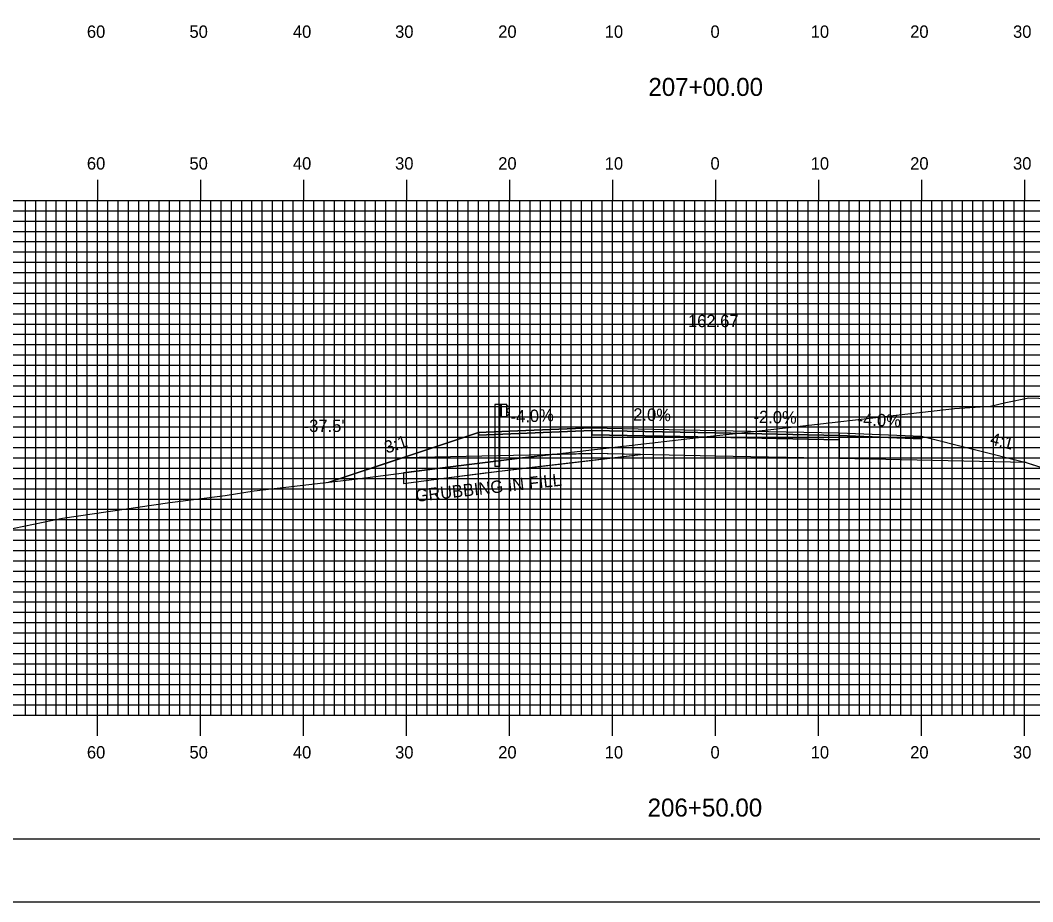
# Model space of a CAD drawing. Extents: x 1793666 to 1794009, y 442591 to 442811.
# Drawn here: x 1793763.8 to 1793862.1, y 442590.5 to 442676.2 of the extents above; entities that cross this region are included whole.
import ezdxf

# ---------------------------------------------------------------- set-up
doc = ezdxf.new("R2010")
doc.units = 0
for name, color, linetype in [('ANNOTATION', 7, 'Continuous'), ('BORDER', 7, 'Continuous'), ('D_Guardrail_Beam_Lt', 7, 'Continuous'), ('D_Roadway_Centerline', 7, 'Continuous'), ('D_Roadway_Centerline_Text', 7, 'Continuous'), ('D_Roadway_Edge_Shoulder', 7, 'Continuous'), ('D_Roadway_Edge_TW', 7, 'Continuous'), ('D_Roadway_FinishedGrade', 7, 'Continuous'), ('D_Roadway_Pavement', 7, 'Continuous'), ('D_Roadway_SlopeLines', 7, 'Continuous'), ('D_Roadway_SubGrade', 7, 'Continuous'), ('D_Text_Standard', 7, 'Continuous'), ('GRUBBING IN FILL', 7, 'Continuous'), ('H_V ANNOTATION', 7, 'Continuous'), ('MAJOR', 7, 'Continuous'), ('MINOR', 7, 'Continuous'), ('PLOT BOUNDARY', 7, 'Continuous'), ('S_Roadway_Centerline', 7, 'Continuous')]:
    doc.layers.add(name, color=color, linetype=linetype)

msp = doc.modelspace()

# ---------------------------------------------------------------- linework, layer by layer
at = {"layer": 'BORDER'}
msp.add_lwpolyline([(1793681.714, 442596.665), (1794001.714, 442596.665), (1794001.714, 442806.665), (1793681.714, 442806.665)], close=True, dxfattribs=at)
at = {"layer": 'D_Guardrail_Beam_Lt'}
for p, q in [((1793809.884, 442638.836), (1793809.884, 442632.836)), ((1793810.355, 442638.836), (1793809.884, 442638.836)), ((1793811.043, 442638.836), (1793810.355, 442638.836)), ((1793810.355, 442638.836), (1793810.355, 442637.669)), ((1793810.418, 442638.836), (1793810.418, 442637.669)), ((1793810.522, 442638.836), (1793810.522, 442637.669)), ((1793811.043, 442637.669), (1793811.043, 442638.836)), ((1793811.043, 442638.752), (1793811.117, 442638.738)), ((1793811.047, 442638.288), (1793811.047, 442638.217)), ((1793811.276, 442638.488), (1793811.081, 442638.352)), ((1793811.081, 442638.153), (1793811.276, 442638.017)), ((1793811.133, 442638.731), (1793811.276, 442638.631)), ((1793811.276, 442637.874), (1793811.133, 442637.774)), ((1793810.355, 442637.669), (1793811.043, 442637.669)), ((1793810.376, 442632.836), (1793810.376, 442637.669)), ((1793811.117, 442637.767), (1793811.043, 442637.752)), ((1793810.376, 442632.836), (1793809.884, 442632.836))]:
    msp.add_line(p, q, dxfattribs=at)
for centre, major_axis, start_param, end_param in [((1793811.126, 442638.288), (-0.0789, 0), 5.323254, 6.283185), ((1793811.126, 442638.217), (-0.0789, 0), 6.283185, 7.243116), ((1793811.109, 442638.697), (0.0417, 0), 0.959931, 1.376053), ((1793811.226, 442638.56), (0.0877, 0), 5.323254, 7.243116), ((1793811.226, 442637.945), (0.0877, 0), 5.323254, 7.243116), ((1793811.109, 442637.808), (0.0417, 0), 4.907132, 5.323254)]:
    msp.add_ellipse(centre, major_axis=major_axis, ratio=0.995501, start_param=start_param, end_param=end_param, dxfattribs=at)
at = {"layer": 'D_Roadway_Centerline'}
msp.add_lwpolyline([(1793793.811, 442631.298), (1793801.037, 442633.707), (1793808.314, 442636.132), (1793811.314, 442636.252), (1793819.314, 442636.572), (1793831.314, 442636.332), (1793843.314, 442636.092), (1793851.314, 442635.772), (1793861.488, 442633.229), (1793865.388, 442631.947), (1793869.289, 442630.665)], dxfattribs=at)
at = {"layer": 'D_Roadway_Edge_Shoulder'}
for points in [[(1793819.314, 442636.572), (1793811.314, 442636.252), (1793811.314, 442636.252), (1793808.314, 442636.132), (1793808.314, 442635.882), (1793819.314, 442636.322)], [(1793843.314, 442636.092), (1793851.314, 442635.772), (1793851.314, 442635.522), (1793843.314, 442635.842)]]:
    msp.add_lwpolyline(points, close=True, dxfattribs=at)
at = {"layer": 'D_Roadway_Edge_TW'}
msp.add_lwpolyline([(1793819.314, 442636.322), (1793819.314, 442636.572), (1793831.314, 442636.332), (1793843.314, 442636.092), (1793843.314, 442635.842), (1793831.314, 442636.082)], close=True, dxfattribs=at)
at = {"layer": 'D_Roadway_FinishedGrade'}
msp.add_line((1793861.488, 442633.229), (1793869.289, 442630.665), dxfattribs=at)
msp.add_line((1793861.488, 442633.229), (1793869.289, 442630.665), dxfattribs=at)
at = {"layer": 'D_Roadway_Pavement'}
msp.add_lwpolyline([(1793819.314, 442635.906), (1793819.314, 442636.322), (1793831.314, 442636.082), (1793843.314, 442635.842), (1793843.314, 442635.426), (1793831.314, 442635.666)], close=True, dxfattribs=at)
for points in [[(1793819.314, 442636.322), (1793819.314, 442635.906)], [(1793843.314, 442635.842), (1793843.314, 442635.426)]]:
    msp.add_lwpolyline(points, dxfattribs=at)
at = {"layer": 'D_Roadway_SlopeLines'}
msp.add_line((1793851.314, 442635.772), (1793861.488, 442633.229), dxfattribs=at)
msp.add_lwpolyline([(1793808.314, 442636.132), (1793793.616, 442631.233)], dxfattribs=at)
at = {"layer": 'D_Roadway_SubGrade'}
for points in [[(1793819.314, 442635.906), (1793819.314, 442636.322), (1793808.314, 442635.882), (1793808.314, 442636.132), (1793801.037, 442633.707), (1793819.314, 442634.072)], [(1793819.314, 442634.072), (1793819.314, 442636.322), (1793819.314, 442635.906), (1793831.314, 442635.666), (1793843.314, 442635.426), (1793843.314, 442635.842), (1793843.314, 442633.592), (1793831.314, 442633.832)], [(1793843.314, 442635.426), (1793843.314, 442635.842), (1793851.314, 442635.522), (1793851.314, 442635.772), (1793861.488, 442633.229), (1793843.314, 442633.592)]]:
    msp.add_lwpolyline(points, close=True, dxfattribs=at)
at = {"layer": 'GRUBBING IN FILL'}
msp.add_line((1793801.037, 442632.198), (1793801.037, 442631.189), dxfattribs=at)
msp.add_line((1793801.037, 442632.198), (1793801.037, 442631.189), dxfattribs=at)
msp.add_lwpolyline([(1793801.037, 442632.198), (1793801.037, 442631.189), (1793805.196, 442631.73), (1793808.942, 442632.201), (1793818.361, 442633.325), (1793824.034, 442633.978), (1793819.314, 442634.072), (1793815.442, 442633.995), (1793812.568, 442633.664), (1793805.069, 442632.722)], close=True, dxfattribs=at)
msp.add_lwpolyline([(1793801.037, 442632.198), (1793801.037, 442631.189), (1793805.196, 442631.73), (1793808.942, 442632.201), (1793818.361, 442633.325), (1793824.034, 442633.978), (1793819.314, 442634.072), (1793815.442, 442633.995), (1793812.568, 442633.664), (1793805.069, 442632.722)], close=True, dxfattribs=at)
msp.add_lwpolyline([(1793801.037, 442631.189), (1793805.196, 442631.73), (1793812.688, 442632.671), (1793824.034, 442633.978)], dxfattribs=at)
msp.add_lwpolyline([(1793801.037, 442631.189), (1793805.196, 442631.73), (1793812.688, 442632.671), (1793824.034, 442633.978)], dxfattribs=at)
at = {"layer": 'MAJOR'}
for p, q in [((1793771.314, 442660.669), (1793771.314, 442658.665)), ((1793781.314, 442660.669), (1793781.314, 442658.665)), ((1793791.314, 442660.669), (1793791.314, 442658.665)), ((1793801.314, 442660.669), (1793801.314, 442658.665)), ((1793811.314, 442660.669), (1793811.314, 442658.665)), ((1793821.314, 442660.669), (1793821.314, 442658.665)), ((1793831.314, 442660.669), (1793831.314, 442658.665)), ((1793841.314, 442660.669), (1793841.314, 442658.665)), ((1793851.314, 442660.669), (1793851.314, 442658.665)), ((1793861.314, 442660.669), (1793861.314, 442658.665)), ((1793691.314, 442658.665), (1793971.314, 442658.665)), ((1793691.314, 442658.665), (1793971.314, 442658.665)), ((1793771.314, 442608.665), (1793771.314, 442658.665)), ((1793781.314, 442608.665), (1793781.314, 442658.665)), ((1793791.314, 442608.665), (1793791.314, 442658.665)), ((1793801.314, 442608.665), (1793801.314, 442658.665)), ((1793811.314, 442608.665), (1793811.314, 442658.665)), ((1793821.314, 442608.665), (1793821.314, 442658.665)), ((1793831.314, 442608.665), (1793831.314, 442658.665)), ((1793841.314, 442608.665), (1793841.314, 442658.665)), ((1793851.314, 442608.665), (1793851.314, 442658.665)), ((1793861.314, 442608.665), (1793861.314, 442658.665)), ((1793691.314, 442653.665), (1793971.314, 442653.665)), ((1793691.314, 442648.665), (1793971.314, 442648.665)), ((1793691.314, 442643.665), (1793971.314, 442643.665)), ((1793691.314, 442638.665), (1793971.314, 442638.665)), ((1793691.314, 442633.665), (1793971.314, 442633.665)), ((1793691.314, 442628.665), (1793971.314, 442628.665)), ((1793691.314, 442623.665), (1793971.314, 442623.665)), ((1793691.314, 442618.665), (1793971.314, 442618.665)), ((1793691.314, 442613.665), (1793971.314, 442613.665)), ((1793691.314, 442608.665), (1793971.314, 442608.665)), ((1793691.314, 442608.665), (1793971.314, 442608.665)), ((1793771.314, 442606.661), (1793771.314, 442608.665)), ((1793781.314, 442606.661), (1793781.314, 442608.665)), ((1793791.314, 442606.661), (1793791.314, 442608.665)), ((1793801.314, 442606.661), (1793801.314, 442608.665)), ((1793811.314, 442606.661), (1793811.314, 442608.665)), ((1793821.314, 442606.661), (1793821.314, 442608.665)), ((1793831.314, 442606.661), (1793831.314, 442608.665)), ((1793841.314, 442606.661), (1793841.314, 442608.665)), ((1793851.314, 442606.661), (1793851.314, 442608.665)), ((1793861.314, 442606.661), (1793861.314, 442608.665))]:
    msp.add_line(p, q, dxfattribs=at)
at = {"layer": 'MINOR'}
for p, q in [((1793764.314, 442608.665), (1793764.314, 442658.665)), ((1793765.314, 442608.665), (1793765.314, 442658.665)), ((1793766.314, 442608.665), (1793766.314, 442658.665)), ((1793767.314, 442608.665), (1793767.314, 442658.665)), ((1793768.314, 442608.665), (1793768.314, 442658.665)), ((1793769.314, 442608.665), (1793769.314, 442658.665)), ((1793770.314, 442608.665), (1793770.314, 442658.665)), ((1793772.314, 442608.665), (1793772.314, 442658.665)), ((1793773.314, 442608.665), (1793773.314, 442658.665)), ((1793774.314, 442608.665), (1793774.314, 442658.665)), ((1793775.314, 442608.665), (1793775.314, 442658.665)), ((1793776.314, 442608.665), (1793776.314, 442658.665)), ((1793777.314, 442608.665), (1793777.314, 442658.665)), ((1793778.314, 442608.665), (1793778.314, 442658.665)), ((1793779.314, 442608.665), (1793779.314, 442658.665)), ((1793780.314, 442608.665), (1793780.314, 442658.665)), ((1793782.314, 442608.665), (1793782.314, 442658.665)), ((1793783.314, 442608.665), (1793783.314, 442658.665)), ((1793784.314, 442608.665), (1793784.314, 442658.665)), ((1793785.314, 442608.665), (1793785.314, 442658.665)), ((1793786.314, 442608.665), (1793786.314, 442658.665)), ((1793787.314, 442608.665), (1793787.314, 442658.665)), ((1793788.314, 442608.665), (1793788.314, 442658.665)), ((1793789.314, 442608.665), (1793789.314, 442658.665)), ((1793790.314, 442608.665), (1793790.314, 442658.665)), ((1793792.314, 442608.665), (1793792.314, 442658.665)), ((1793793.314, 442608.665), (1793793.314, 442658.665)), ((1793794.314, 442608.665), (1793794.314, 442658.665)), ((1793795.314, 442608.665), (1793795.314, 442658.665)), ((1793796.314, 442608.665), (1793796.314, 442658.665)), ((1793797.314, 442608.665), (1793797.314, 442658.665)), ((1793798.314, 442608.665), (1793798.314, 442658.665)), ((1793799.314, 442608.665), (1793799.314, 442658.665)), ((1793800.314, 442608.665), (1793800.314, 442658.665)), ((1793802.314, 442608.665), (1793802.314, 442658.665)), ((1793803.314, 442608.665), (1793803.314, 442658.665)), ((1793804.314, 442608.665), (1793804.314, 442658.665)), ((1793805.314, 442608.665), (1793805.314, 442658.665)), ((1793806.314, 442608.665), (1793806.314, 442658.665)), ((1793807.314, 442608.665), (1793807.314, 442658.665)), ((1793808.314, 442608.665), (1793808.314, 442658.665)), ((1793809.314, 442608.665), (1793809.314, 442658.665)), ((1793810.314, 442608.665), (1793810.314, 442658.665)), ((1793812.314, 442608.665), (1793812.314, 442658.665)), ((1793813.314, 442608.665), (1793813.314, 442658.665)), ((1793814.314, 442608.665), (1793814.314, 442658.665)), ((1793815.314, 442608.665), (1793815.314, 442658.665)), ((1793816.314, 442608.665), (1793816.314, 442658.665)), ((1793817.314, 442608.665), (1793817.314, 442658.665)), ((1793818.314, 442608.665), (1793818.314, 442658.665)), ((1793819.314, 442608.665), (1793819.314, 442658.665)), ((1793820.314, 442608.665), (1793820.314, 442658.665)), ((1793822.314, 442608.665), (1793822.314, 442658.665)), ((1793823.314, 442608.665), (1793823.314, 442658.665)), ((1793824.314, 442608.665), (1793824.314, 442658.665)), ((1793825.314, 442608.665), (1793825.314, 442658.665)), ((1793826.314, 442608.665), (1793826.314, 442658.665)), ((1793827.314, 442608.665), (1793827.314, 442658.665)), ((1793828.314, 442608.665), (1793828.314, 442658.665)), ((1793829.314, 442608.665), (1793829.314, 442658.665)), ((1793830.314, 442608.665), (1793830.314, 442658.665)), ((1793832.314, 442608.665), (1793832.314, 442658.665)), ((1793833.314, 442608.665), (1793833.314, 442658.665)), ((1793834.314, 442608.665), (1793834.314, 442658.665)), ((1793835.314, 442608.665), (1793835.314, 442658.665)), ((1793836.314, 442608.665), (1793836.314, 442658.665)), ((1793837.314, 442608.665), (1793837.314, 442658.665)), ((1793838.314, 442608.665), (1793838.314, 442658.665)), ((1793839.314, 442608.665), (1793839.314, 442658.665)), ((1793840.314, 442608.665), (1793840.314, 442658.665)), ((1793842.314, 442608.665), (1793842.314, 442658.665)), ((1793843.314, 442608.665), (1793843.314, 442658.665)), ((1793844.314, 442608.665), (1793844.314, 442658.665)), ((1793845.314, 442608.665), (1793845.314, 442658.665)), ((1793846.314, 442608.665), (1793846.314, 442658.665)), ((1793847.314, 442608.665), (1793847.314, 442658.665)), ((1793848.314, 442608.665), (1793848.314, 442658.665)), ((1793849.314, 442608.665), (1793849.314, 442658.665)), ((1793850.314, 442608.665), (1793850.314, 442658.665)), ((1793852.314, 442608.665), (1793852.314, 442658.665)), ((1793853.314, 442608.665), (1793853.314, 442658.665)), ((1793854.314, 442608.665), (1793854.314, 442658.665)), ((1793855.314, 442608.665), (1793855.314, 442658.665)), ((1793856.314, 442608.665), (1793856.314, 442658.665)), ((1793857.314, 442608.665), (1793857.314, 442658.665)), ((1793858.314, 442608.665), (1793858.314, 442658.665)), ((1793859.314, 442608.665), (1793859.314, 442658.665)), ((1793860.314, 442608.665), (1793860.314, 442658.665)), ((1793691.314, 442657.665), (1793971.314, 442657.665)), ((1793691.314, 442656.665), (1793971.314, 442656.665)), ((1793691.314, 442655.665), (1793971.314, 442655.665)), ((1793691.314, 442654.665), (1793971.314, 442654.665)), ((1793691.314, 442652.665), (1793971.314, 442652.665)), ((1793691.314, 442651.665), (1793971.314, 442651.665)), ((1793691.314, 442650.665), (1793971.314, 442650.665)), ((1793691.314, 442649.665), (1793971.314, 442649.665)), ((1793691.314, 442647.665), (1793971.314, 442647.665)), ((1793691.314, 442646.665), (1793971.314, 442646.665)), ((1793691.314, 442645.665), (1793971.314, 442645.665)), ((1793691.314, 442644.665), (1793971.314, 442644.665)), ((1793691.314, 442642.665), (1793971.314, 442642.665)), ((1793691.314, 442641.665), (1793971.314, 442641.665)), ((1793691.314, 442640.665), (1793971.314, 442640.665)), ((1793691.314, 442639.665), (1793971.314, 442639.665)), ((1793691.314, 442637.665), (1793971.314, 442637.665)), ((1793691.314, 442636.665), (1793971.314, 442636.665)), ((1793691.314, 442635.665), (1793971.314, 442635.665)), ((1793691.314, 442634.665), (1793971.314, 442634.665)), ((1793691.314, 442632.665), (1793971.314, 442632.665)), ((1793691.314, 442631.665), (1793971.314, 442631.665)), ((1793691.314, 442630.665), (1793971.314, 442630.665)), ((1793691.314, 442629.665), (1793971.314, 442629.665)), ((1793691.314, 442627.665), (1793971.314, 442627.665)), ((1793691.314, 442626.665), (1793971.314, 442626.665)), ((1793691.314, 442625.665), (1793971.314, 442625.665)), ((1793691.314, 442624.665), (1793971.314, 442624.665)), ((1793691.314, 442622.665), (1793971.314, 442622.665)), ((1793691.314, 442621.665), (1793971.314, 442621.665)), ((1793691.314, 442620.665), (1793971.314, 442620.665)), ((1793691.314, 442619.665), (1793971.314, 442619.665)), ((1793691.314, 442617.665), (1793971.314, 442617.665)), ((1793691.314, 442616.665), (1793971.314, 442616.665)), ((1793691.314, 442615.665), (1793971.314, 442615.665)), ((1793691.314, 442614.665), (1793971.314, 442614.665)), ((1793691.314, 442612.665), (1793971.314, 442612.665)), ((1793691.314, 442611.665), (1793971.314, 442611.665)), ((1793691.314, 442610.665), (1793971.314, 442610.665)), ((1793691.314, 442609.665), (1793971.314, 442609.665))]:
    msp.add_line(p, q, dxfattribs=at)
at = {"layer": 'PLOT BOUNDARY'}
msp.add_lwpolyline([(1793665.527, 442590.547), (1794005.527, 442590.547), (1794005.527, 442810.547), (1793665.527, 442810.547)], close=True, dxfattribs=at)
at = {"layer": 'S_Roadway_Centerline'}
msp.add_lwpolyline([(1793691.314, 442616.321), (1793694.735, 442616.634), (1793705.906, 442617.941), (1793713.058, 442618.85), (1793720.307, 442619.904), (1793734.893, 442621.964), (1793742.87, 442623.311), (1793760.386, 442626.267), (1793767.9, 442627.802), (1793778.333, 442629.328), (1793783.719, 442630.008), (1793786.541, 442630.469), (1793796.306, 442631.583), (1793805.069, 442632.722), (1793812.568, 442633.664), (1793830.499, 442635.729), (1793833.572, 442636.072), (1793854.537, 442638.443), (1793858.019, 442638.691), (1793859.506, 442639.026), (1793861.747, 442639.479), (1793863.669, 442639.425)], dxfattribs=at)

# ---------------------------------------------------------------- texts
at = {"layer": 'ANNOTATION'}
for s, rotation, p in [('-4.0%', 2.29061, (1793811.445, 442637.059)), ('2.0%', 358.85424, (1793823.321, 442637.293)), ('-2.0%', 358.85424, (1793835, 442637.059)), ('-4.0%', 357.70939, (1793845.105, 442636.822)), ('4:1', 345.96376, (1793857.906, 442634.986)), ('3:1', 18.43482, (1793799.401, 442634.07))]:
    msp.add_text(s, height=1.2, rotation=rotation, dxfattribs=at).set_placement(p)
at = {"layer": 'D_Roadway_Centerline'}
for s, p in [('C', (1793831.308, 442636.332)), ('L', (1793831.314, 442636.325))]:
    msp.add_text(s, height=0.0146, dxfattribs=at).set_placement(p)
at = {"layer": 'D_Roadway_Centerline_Text'}
msp.add_text('162.67', height=1.2, dxfattribs=at).set_placement((1793828.649, 442646.362))
at = {"layer": 'D_Text_Standard'}
msp.add_text("-37.5'", height=1.2, dxfattribs=at).set_placement((1793791.333, 442636.177))
at = {"layer": 'GRUBBING IN FILL'}
msp.add_text('GRUBBING IN FILL', height=1.2, rotation=6.33568, dxfattribs=at).set_placement((1793802.26, 442629.388))
at = {"layer": 'H_V ANNOTATION'}
for s, height, p in [('60', 1.2, (1793770.286, 442674.465)), ('50', 1.2, (1793780.243, 442674.465)), ('40', 1.2, (1793790.286, 442674.465)), ('30', 1.2, (1793800.211, 442674.465)), ('20', 1.2, (1793810.222, 442674.465)), ('10', 1.2, (1793820.564, 442674.465)), ('0', 1.2, (1793830.832, 442674.465)), ('10', 1.2, (1793840.564, 442674.465)), ('20', 1.2, (1793850.222, 442674.465)), ('30', 1.2, (1793860.211, 442674.465)), ('207+00.00', 1.75, (1793824.805, 442668.821)), ('60', 1.2, (1793770.286, 442661.665)), ('50', 1.2, (1793780.243, 442661.665)), ('40', 1.2, (1793790.286, 442661.665)), ('30', 1.2, (1793800.211, 442661.665)), ('20', 1.2, (1793810.222, 442661.665)), ('10', 1.2, (1793820.564, 442661.665)), ('0', 1.2, (1793830.832, 442661.665)), ('10', 1.2, (1793840.564, 442661.665)), ('20', 1.2, (1793850.222, 442661.665)), ('30', 1.2, (1793860.211, 442661.665)), ('60', 1.2, (1793770.286, 442604.465)), ('50', 1.2, (1793780.243, 442604.465)), ('40', 1.2, (1793790.286, 442604.465)), ('30', 1.2, (1793800.211, 442604.465)), ('20', 1.2, (1793810.222, 442604.465)), ('10', 1.2, (1793820.564, 442604.465)), ('0', 1.2, (1793830.832, 442604.465)), ('10', 1.2, (1793840.564, 442604.465)), ('20', 1.2, (1793850.222, 442604.465)), ('30', 1.2, (1793860.211, 442604.465)), ('206+50.00', 1.75, (1793824.728, 442598.821))]:
    msp.add_text(s, height=height, dxfattribs=at).set_placement(p)

doc.saveas('drawing.dxf')
